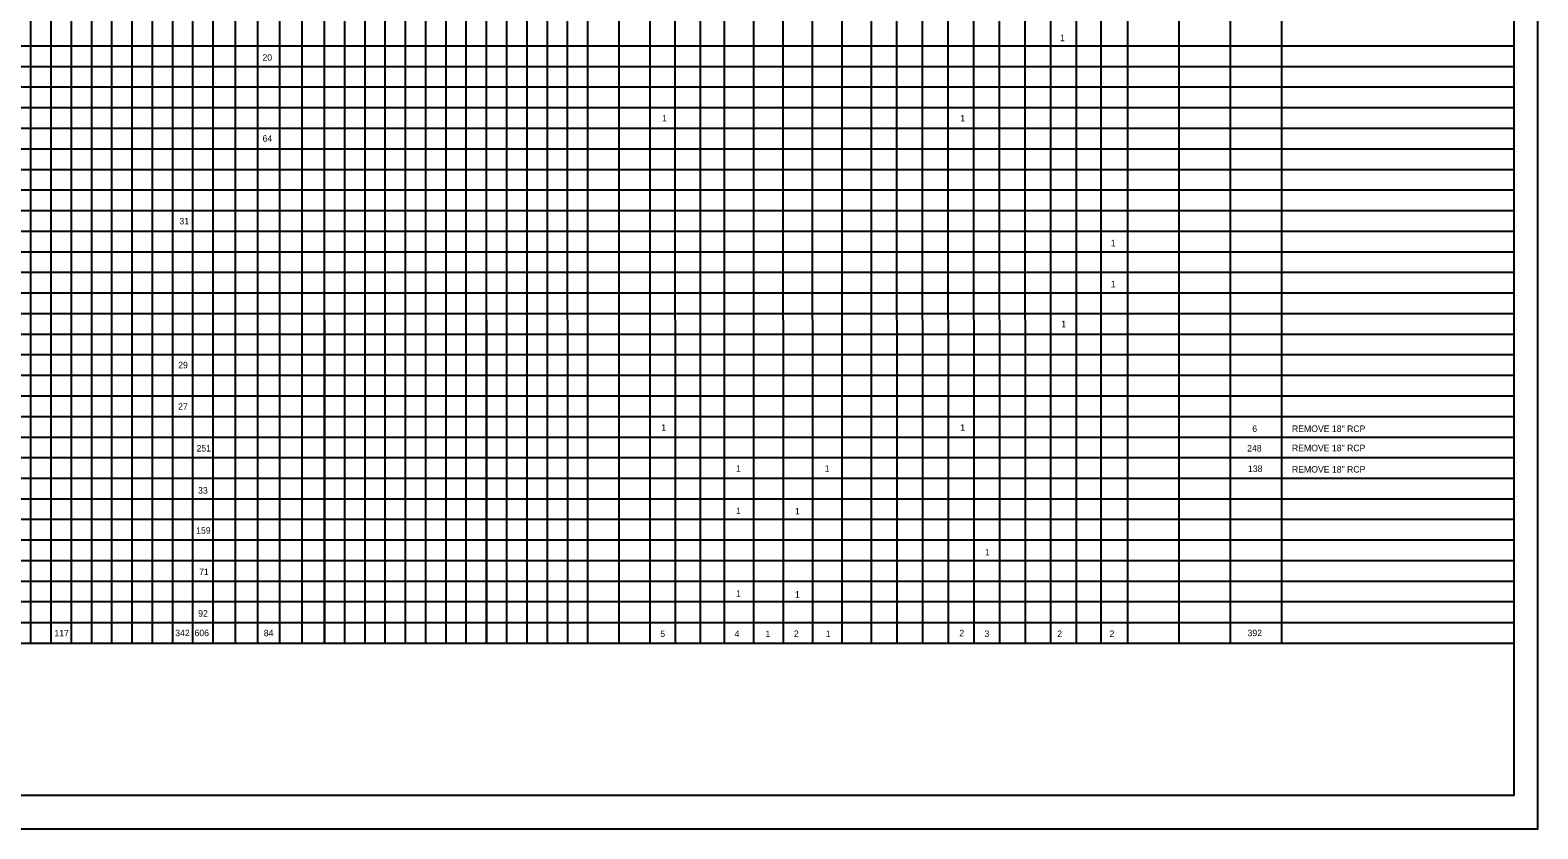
# Model space of a CAD drawing. Extents: x 809447 to 814738, y 647528 to 651206.
# Drawn here: x 810014 to 811131, y 650017 to 650609 of the extents above; entities that cross this region are included whole.
import ezdxf

# ---------------------------------------------------------------- set-up
doc = ezdxf.new("R2010")
doc.units = 0
doc.layers.add('Default', color=7, linetype='Continuous')

msp = doc.modelspace()

# ---------------------------------------------------------------- linework, layer by layer
at = {"layer": 'Default'}
for p, q in [((810014.9, 650154.3), (810014.9, 650925)), ((810119.9, 650154.3), (810119.9, 650925)), ((810232.5, 650154.3), (810232.4, 650925.1)), ((810352.5, 650154.3), (810352.4, 650925.1)), ((810367.5, 650154.3), (810367.4, 650925.1)), ((810382.5, 650154.3), (810382.4, 650925.1)), ((810397.5, 650154.3), (810397.4, 650925.1)), ((810412.5, 650154.3), (810412.4, 650925.1)), ((810427.5, 650154.3), (810427.4, 650925.1)), ((810427.4, 650154.3), (810427.4, 650925.1)), ((810427.5, 650154.3), (810427.4, 650925.1)), ((810473.7, 650154.3), (810473.6, 650925)), ((810528.7, 650154.3), (810528.6, 650925)), ((810528.7, 650154.3), (810528.6, 650925)), ((810550.5, 650154.3), (810550.5, 650925)), ((810637.5, 650154.3), (810637.4, 650925)), ((810675.5, 650154.3), (810675.4, 650925)), ((810694.5, 650154.3), (810694.4, 650925)), ((810713.5, 650154.3), (810713.4, 650925)), ((810732.5, 650154.3), (810732.4, 650925)), ((810751.5, 650154.3), (810751.4, 650925)), ((810770.5, 650154.3), (810770.4, 650925)), ((810789.5, 650154.3), (810789.4, 650925)), ((810807.6, 650155.2), (810807.5, 650925.9)), ((810827.5, 650154.3), (810827.4, 650925)), ((810827.5, 650154.3), (810827.4, 650925)), ((810865.5, 650154.3), (810865.4, 650925)), ((810865.5, 650154.3), (810865.4, 650925)), ((810903.5, 650154.3), (810903.4, 650925)), ((810903.5, 650154.3), (810903.4, 650925)), ((810941.5, 650154.3), (810941.4, 650925)), ((810941.5, 650154.3), (810941.4, 650925)), ((810492.3, 650154.3), (810492.2, 650834.3)), ((810656.5, 650154.3), (810656.4, 650834.3)), ((810029.9, 650154.3), (810029.9, 650817.1)), ((810044.9, 650154.3), (810044.9, 650817.2)), ((810059.9, 650154.3), (810059.9, 650817.1)), ((810074.9, 650154.3), (810074.9, 650817.2)), ((810089.9, 650154.3), (810089.9, 650817.1)), ((810104.9, 650154.3), (810104.9, 650817.2)), ((810119.9, 650154.3), (810119.9, 650817.1)), ((810134.9, 650154.3), (810134.9, 650817.2)), ((810149.9, 650154.3), (810149.9, 650817.2)), ((810166.4, 650154.3), (810166.4, 650817.2)), ((810182.9, 650154.3), (810182.9, 650817.2)), ((810199.4, 650154.3), (810199.4, 650817.2)), ((810215.9, 650154.3), (810215.9, 650817.2)), ((810232.4, 650154.3), (810232.4, 650817.2)), ((810247.4, 650154.3), (810247.4, 650817.2)), ((810262.4, 650154.3), (810262.4, 650817.2)), ((810277.4, 650154.3), (810277.4, 650817.2)), ((810292.4, 650154.3), (810292.4, 650817.2)), ((810307.4, 650154.3), (810307.4, 650817.2)), ((810322.4, 650154.3), (810322.4, 650817.2)), ((810337.4, 650154.3), (810337.4, 650817.2)), ((810352.4, 650154.3), (810352.4, 650817.2)), ((810510.9, 650154.3), (810510.8, 650811.1)), ((810014.9, 650154.3), (810014.9, 650791.8)), ((810450.6, 650154.3), (810450.5, 650791.8)), ((810572.3, 650154.3), (810572.2, 650749)), ((810594, 650154.3), (810593.9, 650749)), ((810615.7, 650154.3), (810615.7, 650749)), ((811113.6, 650597.3), (809613.6, 650597.3)), ((811113.6, 650582), (809613.6, 650582)), ((811113.6, 650566.7), (809613.6, 650566.7)), ((811113.6, 650551.5), (809613.6, 650551.5)), ((811113.6, 650536.2), (809613.6, 650536.2)), ((811113.6, 650520.9), (809613.6, 650520.9)), ((811113.6, 650505.6), (809613.6, 650505.6)), ((811113.6, 650490.4), (809613.6, 650490.4)), ((811113.6, 650475.1), (809613.6, 650475.1)), ((811113.6, 650459.8), (809613.6, 650459.8)), ((811113.6, 650444.5), (809613.6, 650444.5)), ((811113.6, 650429.3), (809613.6, 650429.3)), ((811113.6, 650414), (809613.6, 650414)), ((811113.6, 650398.8), (809613.6, 650398.8)), ((811113.6, 650383.5), (809613.6, 650383.5)), ((811113.6, 650368.3), (809613.6, 650368.3)), ((811113.6, 650353), (809613.6, 650353)), ((811113.6, 650337.8), (809613.6, 650337.8)), ((811113.6, 650322.5), (809613.6, 650322.5)), ((811113.6, 650307.2), (809613.6, 650307.2)), ((811113.6, 650291.9), (809613.6, 650291.9)), ((811113.6, 650276.7), (809613.6, 650276.7)), ((811113.6, 650261.4), (809613.6, 650261.4)), ((811113.6, 650246.2), (809613.6, 650246.2)), ((811113.6, 650230.9), (809613.6, 650230.9)), ((811113.6, 650215.7), (809613.6, 650215.7)), ((811113.6, 650200.4), (809613.6, 650200.4)), ((811113.6, 650185.2), (809613.6, 650185.2)), ((811113.6, 650169.6), (809613.6, 650169.6)), ((811113.6, 650154.3), (809613.6, 650154.3)), ((811113.6, 650154.3), (809613.6, 650154.3))]:
    msp.add_line(p, q, dxfattribs=at)
for points in [[(811131.1, 651116.9), (809447.1, 651116.9), (809447.1, 650016.9), (811131.1, 650016.9)], [(811113.6, 651091.9), (809613.6, 651091.9), (809613.6, 650041.9), (811113.6, 650041.9)]]:
    msp.add_lwpolyline(points, close=True, dxfattribs=at)

# ---------------------------------------------------------------- texts
for s, p in [('1', (810777.2, 650600.9)), ('20', (810186.4, 650586.4)), ('1', (810482.4, 650541.4)), ('1', (810703.3, 650541.4)), ('64', (810186.5, 650526.4)), ('31', (810124.9, 650465.1)), ('1', (810814.8, 650448.9)), ('1', (810814.8, 650418.5)), ('1', (810778.1, 650388.8)), ('29', (810124, 650358.4)), ('27', (810123.9, 650327.6)), ('1', (810481.8, 650312.1)), ('1', (810703.3, 650312.1)), ('6', (810919.6, 650311.2)), ('REMOVE 18" RCP', (810949, 650311.2)), ('251', (810137.6, 650296.7)), ('248', (810915.8, 650296.7)), ('REMOVE 18" RCP', (810949, 650296.9)), ('1', (810537.2, 650281.7)), ('1', (810602.9, 650281.7)), ('138', (810916.4, 650281.5)), ('REMOVE 18" RCP', (810949, 650281.1)), ('33', (810138.7, 650265.5)), ('1', (810537.2, 650250.3)), ('1', (810580.8, 650250.1)), ('159', (810137.3, 650235.8)), ('1', (810721.5, 650219.7)), ('71', (810139.5, 650205.1)), ('1', (810537.2, 650189.1)), ('1', (810580.8, 650188.4)), ('92', (810138.8, 650174.3)), ('117', (810032.3, 650159.6)), ('342', (810121.8, 650159.8)), ('606', (810136.1, 650159.8)), ('84', (810187.4, 650159.7)), ('5', (810481.1, 650159.2)), ('4', (810536.1, 650159.2)), ('1', (810559, 650159.2)), ('2', (810580.1, 650159.2)), ('1', (810603.6, 650159.2)), ('2', (810702.6, 650159.7)), ('3', (810721.2, 650159.2)), ('2', (810775.1, 650159.2)), ('2', (810813.9, 650159.2)), ('392', (810916.1, 650159.8))]:
    msp.add_text(s, height=4.8, dxfattribs=at).set_placement(p)

doc.saveas('drawing.dxf')
